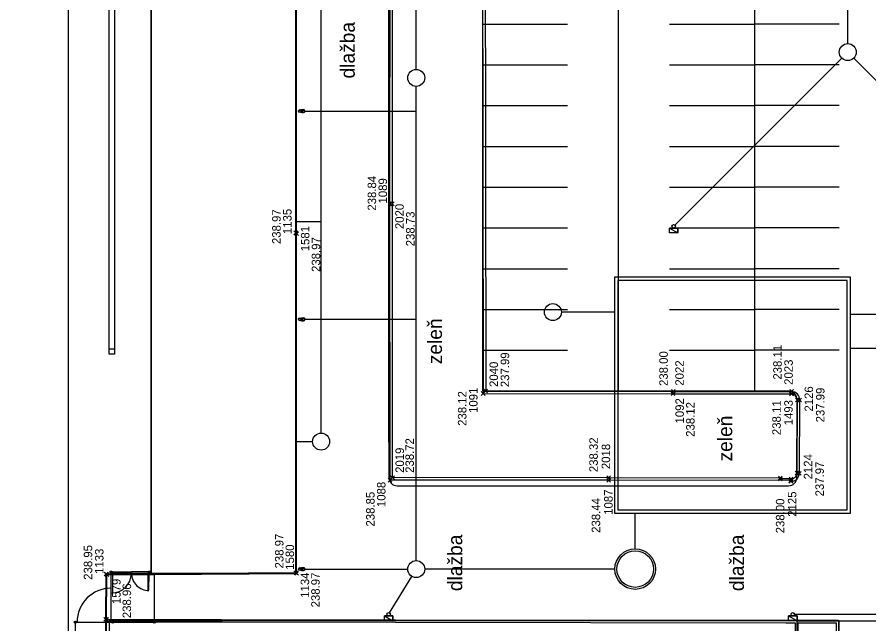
# Model space of a CAD drawing. Extents: x -264205 to -263659, y -1242401 to -1241986.
# Drawn here: x -263975.5 to -263925.3, y -1242255.2 to -1242219.4 of the extents above; entities that cross this region are included whole.
import ezdxf

# ---------------------------------------------------------------- set-up
doc = ezdxf.new("R2010")
doc.units = 0
for name, color, linetype in [('BOD_CISLO_2-3', 7, 'Continuous'), ('BOD_SYMBOL_2-3', 7, 'Continuous'), ('BOD_VYSKA_2-3', 7, 'Continuous'), ('POPIS_2-3', 7, 'Continuous'), ('PROJEKT_OBRUBNIKY_KOMUNIKACIE', 7, 'Continuous'), ('PROJEKT_TDZ_VODOROVNE', 7, 'Continuous'), ('SITUACIA_DSP_2D', 7, 'Continuous'), ('SO_20-2_OBRUBNIKY_DOLNA_HRANA', 7, 'Continuous'), ('SO_20-2_OBRUBNIKY_HORNA_HRANA', 7, 'Continuous'), ('SO_20-4_OBRUBNIKY_DOLNA_HRANA', 7, 'Continuous'), ('SO_20-4_OBRUBNIKY_HORNA_HRANA', 7, 'Continuous')]:
    doc.layers.add(name, color=color, linetype=linetype)

msp = doc.modelspace()

# ---------------------------------------------------------------- linework, layer by layer
at = {"layer": 'BOD_SYMBOL_2-3'}
for p, q in [((-263953.437, -1242230.556), (-263953.658, -1242230.335)), ((-263953.437, -1242230.335), (-263953.658, -1242230.556)), ((-263953.292, -1242230.551), (-263953.514, -1242230.329)), ((-263953.292, -1242230.329), (-263953.514, -1242230.551)), ((-263958.979, -1242232.254), (-263959.199, -1242232.032)), ((-263958.979, -1242232.032), (-263959.199, -1242232.254)), ((-263958.933, -1242232.301), (-263959.155, -1242232.079)), ((-263958.933, -1242232.079), (-263959.155, -1242232.301)), ((-263947.949, -1242241.711), (-263948.171, -1242241.49)), ((-263947.949, -1242241.49), (-263948.171, -1242241.711)), ((-263947.797, -1242241.57), (-263948.019, -1242241.35)), ((-263947.797, -1242241.35), (-263948.019, -1242241.57)), ((-263936.778, -1242241.725), (-263936.998, -1242241.505)), ((-263936.778, -1242241.505), (-263936.998, -1242241.725)), ((-263936.756, -1242241.586), (-263936.976, -1242241.366)), ((-263936.756, -1242241.366), (-263936.976, -1242241.586)), ((-263929.792, -1242241.738), (-263930.014, -1242241.518)), ((-263929.792, -1242241.518), (-263930.014, -1242241.738)), ((-263929.786, -1242241.593), (-263930.008, -1242241.372)), ((-263929.786, -1242241.372), (-263930.008, -1242241.593)), ((-263929.458, -1242242.093), (-263929.678, -1242241.872)), ((-263929.458, -1242241.872), (-263929.678, -1242242.093)), ((-263929.311, -1242242.096), (-263929.531, -1242241.876)), ((-263929.311, -1242241.876), (-263929.531, -1242242.096)), ((-263929.475, -1242246.394), (-263929.696, -1242246.173)), ((-263929.475, -1242246.173), (-263929.696, -1242246.394)), ((-263929.334, -1242246.4), (-263929.555, -1242246.18)), ((-263929.334, -1242246.18), (-263929.555, -1242246.4)), ((-263953.428, -1242246.809), (-263953.649, -1242246.588)), ((-263953.428, -1242246.588), (-263953.649, -1242246.809)), ((-263953.286, -1242246.663), (-263953.508, -1242246.441)), ((-263953.286, -1242246.441), (-263953.508, -1242246.663)), ((-263940.557, -1242246.812), (-263940.778, -1242246.592)), ((-263940.557, -1242246.592), (-263940.778, -1242246.812)), ((-263940.552, -1242246.671), (-263940.773, -1242246.45)), ((-263940.552, -1242246.45), (-263940.773, -1242246.671)), ((-263930.45, -1242246.688), (-263930.671, -1242246.467)), ((-263930.45, -1242246.467), (-263930.671, -1242246.688)), ((-263930.45, -1242246.738), (-263930.671, -1242246.516)), ((-263930.45, -1242246.516), (-263930.671, -1242246.738)), ((-263930.45, -1242246.738), (-263930.671, -1242246.516)), ((-263930.45, -1242246.516), (-263930.671, -1242246.738)), ((-263929.835, -1242246.835), (-263930.057, -1242246.613)), ((-263929.835, -1242246.613), (-263930.057, -1242246.835)), ((-263929.835, -1242246.879), (-263930.057, -1242246.657)), ((-263929.835, -1242246.657), (-263930.057, -1242246.879)), ((-263929.835, -1242246.879), (-263930.057, -1242246.657)), ((-263929.835, -1242246.657), (-263930.057, -1242246.879)), ((-263929.83, -1242246.735), (-263930.052, -1242246.514)), ((-263929.83, -1242246.514), (-263930.052, -1242246.735)), ((-263970.145, -1242252.329), (-263970.367, -1242252.107)), ((-263970.145, -1242252.107), (-263970.367, -1242252.329)), ((-263970.101, -1242252.376), (-263970.322, -1242252.154)), ((-263970.101, -1242252.154), (-263970.322, -1242252.376)), ((-263958.98, -1242252.252), (-263959.2, -1242252.031)), ((-263958.98, -1242252.031), (-263959.2, -1242252.252)), ((-263958.935, -1242252.299), (-263959.155, -1242252.078)), ((-263958.935, -1242252.078), (-263959.155, -1242252.299)), ((-263970.16, -1242254.992), (-263970.381, -1242254.772)), ((-263970.16, -1242254.772), (-263970.381, -1242254.992)), ((-263970.115, -1242254.992), (-263970.335, -1242254.772)), ((-263970.115, -1242254.772), (-263970.335, -1242254.992))]:
    msp.add_line(p, q, dxfattribs=at)
at = {"layer": 'PROJEKT_OBRUBNIKY_KOMUNIKACIE'}
for p, q in [((-263948.093, -1242087.901), (-263948.093, -1242241.458)), ((-263953.617, -1242244.458), (-263953.617, -1242093.307)), ((-263930.08, -1242241.458), (-263948.093, -1242241.458)), ((-263929.582, -1242246.53), (-263929.58, -1242241.959)), ((-263953.617, -1242244.458), (-263953.619, -1242246.529)), ((-263953.119, -1242247.03), (-263930.082, -1242247.03)), ((-263929.58, -1242254.982), (-263920.08, -1242254.982)), ((-263927.093, -1242267.983), (-263927.093, -1242254.982))]:
    msp.add_line(p, q, dxfattribs=at)
for points in [[(-264042.568, -1242294.032), (-263972.468, -1242294.032), (-263972.468, -1242187.932), (-264042.568, -1242187.932), (-264042.568, -1242294.032)], [(-263967.597, -1242197.782), (-263959.097, -1242197.782), (-263959.097, -1242252.182), (-263967.597, -1242252.182), (-263967.597, -1242197.782)], [(-263929.58, -1242254.982), (-263970.077, -1242254.982), (-263970.077, -1242263.982), (-263929.58, -1242263.982), (-263929.58, -1242254.982)]]:
    msp.add_lwpolyline(points, dxfattribs=at)
for centre, start, end in [((-263930.08, -1242241.958), 359.9785, 89.9999), ((-263953.119, -1242246.53), 179.9525, 270), ((-263930.082, -1242246.53), 270, 359.9785)]:
    msp.add_arc(centre, 0.5, start, end, dxfattribs=at)
at = {"layer": 'PROJEKT_TDZ_VODOROVNE'}
for p, q in [((-263940.088, -1242241.458), (-263940.09, -1242199.557)), ((-263932.093, -1242200.657), (-263932.093, -1242241.457)), ((-263948.093, -1242219.857), (-263943.093, -1242219.857)), ((-263937.093, -1242219.857), (-263932.093, -1242219.857)), ((-263927.093, -1242219.857), (-263932.093, -1242219.857)), ((-263948.093, -1242222.257), (-263943.093, -1242222.257)), ((-263937.093, -1242222.257), (-263932.093, -1242222.257)), ((-263927.093, -1242222.257), (-263932.093, -1242222.257)), ((-263948.093, -1242224.657), (-263943.093, -1242224.657)), ((-263937.093, -1242224.657), (-263932.093, -1242224.657)), ((-263927.093, -1242224.657), (-263932.093, -1242224.657)), ((-263948.093, -1242227.057), (-263943.093, -1242227.057)), ((-263937.093, -1242227.057), (-263932.093, -1242227.057)), ((-263927.093, -1242227.057), (-263932.093, -1242227.057)), ((-263948.093, -1242229.457), (-263943.093, -1242229.457)), ((-263937.093, -1242229.457), (-263932.093, -1242229.457)), ((-263927.093, -1242229.457), (-263932.093, -1242229.457)), ((-263948.093, -1242231.857), (-263943.093, -1242231.857)), ((-263937.093, -1242231.857), (-263932.093, -1242231.857)), ((-263927.093, -1242231.857), (-263932.093, -1242231.857)), ((-263948.093, -1242234.257), (-263943.093, -1242234.257)), ((-263937.093, -1242234.257), (-263932.093, -1242234.257)), ((-263927.093, -1242234.257), (-263932.093, -1242234.257)), ((-263948.093, -1242236.657), (-263943.093, -1242236.657)), ((-263937.093, -1242236.657), (-263932.093, -1242236.657)), ((-263927.093, -1242236.657), (-263932.093, -1242236.657)), ((-263948.093, -1242239.057), (-263943.093, -1242239.057)), ((-263937.093, -1242239.057), (-263932.093, -1242239.057)), ((-263927.093, -1242239.057), (-263932.093, -1242239.057))]:
    msp.add_line(p, q, dxfattribs=at)
at = {"layer": 'SITUACIA_DSP_2D'}
for p, q in [((-263948.093, -1242087.901), (-263948.093, -1242241.458)), ((-263953.617, -1242244.458), (-263953.617, -1242093.307)), ((-263952, -1242222.527), (-263952, -1242182)), ((-263972.468, -1242294.032), (-263972.468, -1242187.932)), ((-263957.597, -1242243.932), (-263957.597, -1242193.383)), ((-263967.597, -1242252.182), (-263967.597, -1242197.782)), ((-263967.593, -1242252.182), (-263967.593, -1242197.782)), ((-263967.593, -1242252.182), (-263967.593, -1242197.782)), ((-263959.097, -1242197.782), (-263959.093, -1242252.182)), ((-263959.097, -1242197.782), (-263959.097, -1242252.182)), ((-263959.093, -1242197.782), (-263959.093, -1242252.182)), ((-263926.593, -1242221.011), (-263926.593, -1242205.252)), ((-263970.07, -1242239.282), (-263970.071, -1242210.684)), ((-263969.77, -1242210.682), (-263969.77, -1242239.282)), ((-263936.772, -1242231.691), (-263926.947, -1242221.865)), ((-263916.414, -1242231.691), (-263926.24, -1242221.865)), ((-263952, -1242251.432), (-263952, -1242223.527)), ((-263958.799, -1242224.912), (-263958.762, -1242224.912)), ((-263958.799, -1242225.052), (-263958.762, -1242225.052)), ((-263958.762, -1242224.912), (-263958.742, -1242224.892)), ((-263958.762, -1242225.052), (-263958.742, -1242225.072)), ((-263958.742, -1242224.892), (-263958.637, -1242224.892)), ((-263958.742, -1242225.072), (-263958.637, -1242225.072)), ((-263958.575, -1242224.982), (-263952, -1242224.982)), ((-263959.097, -1242231.482), (-263957.597, -1242231.482)), ((-263937.093, -1242231.862), (-263936.593, -1242231.862)), ((-263937.093, -1242232.152), (-263937.093, -1242231.862)), ((-263937.093, -1242231.862), (-263936.593, -1242232.152)), ((-263937.093, -1242231.862), (-263936.593, -1242232.152)), ((-263936.593, -1242231.862), (-263937.093, -1242231.862)), ((-263936.593, -1242232.152), (-263937.093, -1242232.152)), ((-263936.593, -1242231.862), (-263936.593, -1242232.152)), ((-263936.593, -1242232.152), (-263936.593, -1242231.862)), ((-263926.43, -1242234.749), (-263940.33, -1242234.749)), ((-263940.33, -1242234.749), (-263940.33, -1242248.649)), ((-263926.63, -1242234.949), (-263940.13, -1242234.949)), ((-263940.13, -1242234.949), (-263940.13, -1242248.449)), ((-263926.63, -1242248.449), (-263926.63, -1242234.949)), ((-263926.43, -1242248.649), (-263926.43, -1242234.749)), ((-263958.799, -1242237.162), (-263958.762, -1242237.162)), ((-263958.762, -1242237.162), (-263958.742, -1242237.142)), ((-263958.742, -1242237.142), (-263958.637, -1242237.142)), ((-263940.33, -1242236.811), (-263943.454, -1242236.811)), ((-263919.13, -1242236.949), (-263926.43, -1242236.949)), ((-263958.799, -1242237.302), (-263958.762, -1242237.302)), ((-263958.762, -1242237.302), (-263958.742, -1242237.322)), ((-263958.742, -1242237.322), (-263958.637, -1242237.322)), ((-263958.575, -1242237.232), (-263952, -1242237.232)), ((-263969.77, -1242238.982), (-263970.07, -1242238.982)), ((-263907.219, -1242238.949), (-263926.43, -1242238.949)), ((-263969.77, -1242239.282), (-263970.07, -1242239.282)), ((-263930.081, -1242241.458), (-263948.093, -1242241.458)), ((-263929.582, -1242246.53), (-263929.581, -1242241.959)), ((-263959.097, -1242244.432), (-263958.097, -1242244.432)), ((-263953.617, -1242244.458), (-263953.619, -1242246.529)), ((-263953.119, -1242247.03), (-263930.082, -1242247.03)), ((-263940.33, -1242248.649), (-263926.43, -1242248.649)), ((-263940.13, -1242248.449), (-263926.63, -1242248.449)), ((-263939.13, -1242248.649), (-263939.13, -1242250.737)), ((-263970.018, -1242252.152), (-263970.018, -1242252.052)), ((-263970.018, -1242252.052), (-263969.918, -1242252.052)), ((-263969.918, -1242252.152), (-263970.018, -1242252.152)), ((-263970.005, -1242252.14), (-263970.005, -1242252.065)), ((-263970.005, -1242252.065), (-263969.93, -1242252.065)), ((-263969.93, -1242252.14), (-263970.005, -1242252.14)), ((-263969.93, -1242252.14), (-263969.98, -1242252.14)), ((-263969.98, -1242252.14), (-263969.98, -1242252.24)), ((-263969.968, -1242252.152), (-263969.968, -1242252.202)), ((-263969.968, -1242252.202), (-263969.868, -1242252.202)), ((-263969.955, -1242253.327), (-263969.955, -1242252.19)), ((-263969.955, -1242252.19), (-263969.88, -1242252.19)), ((-263969.93, -1242252.065), (-263969.93, -1242252.14)), ((-263969.918, -1242252.052), (-263969.918, -1242252.152)), ((-263969.918, -1242252.102), (-263968.78, -1242252.102)), ((-263969.918, -1242252.177), (-263969.918, -1242252.102)), ((-263968.78, -1242252.177), (-263969.918, -1242252.177)), ((-263969.88, -1242252.19), (-263969.88, -1242253.327)), ((-263969.868, -1242252.202), (-263969.868, -1242252.177)), ((-263968.78, -1242252.102), (-263968.78, -1242252.177)), ((-263967.768, -1242252.102), (-263968.755, -1242252.102)), ((-263968.755, -1242252.102), (-263968.755, -1242252.177)), ((-263968.755, -1242252.177), (-263967.768, -1242252.177)), ((-263967.818, -1242252.202), (-263967.818, -1242252.177)), ((-263967.718, -1242252.202), (-263967.818, -1242252.202)), ((-263967.805, -1242252.19), (-263967.807, -1242253.177)), ((-263967.73, -1242252.19), (-263967.805, -1242252.19)), ((-263967.768, -1242252.152), (-263967.768, -1242252.052)), ((-263967.768, -1242252.052), (-263967.668, -1242252.052)), ((-263967.768, -1242252.177), (-263967.768, -1242252.102)), ((-263967.668, -1242252.152), (-263967.768, -1242252.152)), ((-263967.755, -1242252.14), (-263967.755, -1242252.065)), ((-263967.755, -1242252.065), (-263967.68, -1242252.065)), ((-263967.755, -1242252.14), (-263967.705, -1242252.14)), ((-263967.68, -1242252.14), (-263967.755, -1242252.14)), ((-263967.732, -1242253.177), (-263967.73, -1242252.19)), ((-263967.718, -1242252.152), (-263967.718, -1242252.202)), ((-263967.705, -1242252.14), (-263967.705, -1242252.24)), ((-263967.68, -1242252.065), (-263967.68, -1242252.14)), ((-263967.668, -1242252.052), (-263967.668, -1242252.152)), ((-263959.097, -1242252.182), (-263967.597, -1242252.182)), ((-263959.093, -1242252.182), (-263967.593, -1242252.182)), ((-263959.093, -1242252.182), (-263967.593, -1242252.182)), ((-263967.418, -1242252.182), (-263967.418, -1242255.057)), ((-263958.799, -1242251.862), (-263958.762, -1242251.862)), ((-263958.799, -1242252.002), (-263958.762, -1242252.002)), ((-263958.762, -1242251.862), (-263958.742, -1242251.842)), ((-263958.762, -1242252.002), (-263958.742, -1242252.022)), ((-263958.742, -1242251.842), (-263958.637, -1242251.842)), ((-263958.742, -1242252.022), (-263958.637, -1242252.022)), ((-263958.575, -1242251.932), (-263952.5, -1242251.932)), ((-263940.302, -1242251.932), (-263951.5, -1242251.932)), ((-263969.98, -1242252.24), (-263969.955, -1242252.24)), ((-263967.705, -1242252.24), (-263967.73, -1242252.24)), ((-263953.57, -1242254.506), (-263952.26, -1242252.359)), ((-263969.968, -1242255.057), (-263969.968, -1242253.057)), ((-263953.87, -1242254.692), (-263953.37, -1242254.692)), ((-263953.87, -1242254.982), (-263953.87, -1242254.692)), ((-263953.87, -1242254.692), (-263953.37, -1242254.982)), ((-263953.87, -1242254.692), (-263953.37, -1242254.982)), ((-263953.37, -1242254.692), (-263953.87, -1242254.692)), ((-263953.37, -1242254.692), (-263953.37, -1242254.982)), ((-263953.37, -1242254.982), (-263953.37, -1242254.692)), ((-263930.08, -1242254.692), (-263929.58, -1242254.692)), ((-263930.08, -1242254.982), (-263930.08, -1242254.692)), ((-263930.08, -1242254.692), (-263929.58, -1242254.982)), ((-263930.08, -1242254.692), (-263929.58, -1242254.982)), ((-263929.58, -1242254.692), (-263930.08, -1242254.692)), ((-263929.73, -1242254.592), (-263920.595, -1242254.592)), ((-263929.58, -1242254.692), (-263929.58, -1242254.982)), ((-263929.58, -1242254.982), (-263929.58, -1242254.692)), ((-263972.128, -1242255.057), (-263972.008, -1242255.057)), ((-263972.068, -1242255.117), (-263972.068, -1242254.997)), ((-263972.068, -1242255.057), (-263967.418, -1242255.057)), ((-263972.068, -1242294.432), (-263972.068, -1242255.057)), ((-263929.58, -1242254.982), (-263970.077, -1242254.982)), ((-263970.077, -1242254.982), (-263970.077, -1242263.982)), ((-263969.928, -1242255.057), (-263969.808, -1242255.057)), ((-263969.868, -1242255.117), (-263969.868, -1242254.997)), ((-263967.478, -1242255.057), (-263967.358, -1242255.057)), ((-263967.418, -1242255.117), (-263967.418, -1242254.997)), ((-263953.37, -1242254.982), (-263953.87, -1242254.982)), ((-263929.58, -1242254.982), (-263930.08, -1242254.982)), ((-263929.58, -1242263.982), (-263929.58, -1242254.982))]:
    msp.add_line(p, q, dxfattribs=at)
for centre, radius in [((-263926.593, -1242221.511), 0.5), ((-263952, -1242223.027), 0.5), ((-263958.847, -1242224.982), 0.085), ((-263958.847, -1242224.982), 0.0625), ((-263958.637, -1242224.982), 0.0625), ((-263936.843, -1242231.762), 0.1), ((-263943.954, -1242236.811), 0.5), ((-263958.847, -1242237.232), 0.085), ((-263958.847, -1242237.232), 0.0625), ((-263958.637, -1242237.232), 0.0625), ((-263957.597, -1242244.432), 0.5), ((-263939.107, -1242251.932), 1.195), ((-263939.107, -1242251.932), 1.075), ((-263952, -1242251.932), 0.5), ((-263958.847, -1242251.932), 0.085), ((-263958.847, -1242251.932), 0.0625), ((-263958.637, -1242251.932), 0.0625), ((-263953.62, -1242254.592), 0.1), ((-263929.83, -1242254.592), 0.1), ((-263972.068, -1242255.057), 0.06), ((-263969.868, -1242255.057), 0.06), ((-263967.418, -1242255.057), 0.06)]:
    msp.add_circle(centre, radius, dxfattribs=at)
for centre, radius, start, end in [((-263958.637, -1242224.982), 0.09, 270, 90), ((-263958.637, -1242237.232), 0.09, 270, 90), ((-263930.081, -1242241.958), 0.5, 359.9785, 89.9999), ((-263953.119, -1242246.53), 0.5, 179.9525, 270), ((-263930.082, -1242246.53), 0.5, 270, 359.9785), ((-263969.943, -1242252.165), 1.175, 269.3905, 359.3905), ((-263967.743, -1242252.165), 1.025, 180.6095, 270.6095), ((-263958.637, -1242251.932), 0.09, 270, 90), ((-263969.968, -1242255.057), 2, 90, 180)]:
    msp.add_arc(centre, radius, start, end, dxfattribs=at)
for centre in [(-263969.943, -1242252.165), (-263969.943, -1242252.165), (-263967.743, -1242252.165)]:
    msp.add_ellipse(centre, major_axis=(0, 0.0125), ratio=0.999995, dxfattribs=at)
at = {"layer": 'SO_20-2_OBRUBNIKY_DOLNA_HRANA'}
for p, q in [((-263930.231, -1242255.088), (-263929.686, -1242255.089)), ((-263929.686, -1242255.089), (-263929.727, -1242263.714))]:
    msp.add_line(p, q, dxfattribs=at)
for points in [[(-263970.225, -1242255.029), (-263963.43, -1242255.035), (-263953.224, -1242255.054), (-263930.231, -1242255.088)], [(-263927.183, -1242254.936), (-263927.134, -1242254.939), (-263927.032, -1242263.694)]]:
    msp.add_lwpolyline(points, dxfattribs=at)
at = {"layer": 'SO_20-2_OBRUBNIKY_HORNA_HRANA'}
for p, q in [((-263970.27, -1242254.881), (-263970.225, -1242254.882)), ((-263930.229, -1242254.938), (-263929.52, -1242254.945)), ((-263929.536, -1242255.089), (-263929.577, -1242263.713)), ((-263929.536, -1242255.089), (-263927.277, -1242255.089))]:
    msp.add_line(p, q, dxfattribs=at)
for points in [[(-263970.27, -1242270.832), (-263970.272, -1242265.906), (-263970.272, -1242263.853), (-263970.27, -1242254.881)], [(-263970.227, -1242270.832), (-263970.227, -1242265.907), (-263970.227, -1242263.854), (-263970.225, -1242254.882)], [(-263970.225, -1242254.882), (-263963.483, -1242254.892), (-263953.227, -1242254.91), (-263930.229, -1242254.938)], [(-263929.52, -1242254.945), (-263927.183, -1242254.936)], [(-263927.277, -1242255.089), (-263927.18, -1242263.695)]]:
    msp.add_lwpolyline(points, dxfattribs=at)
at = {"layer": 'SO_20-4_OBRUBNIKY_DOLNA_HRANA'}
for p, q in [((-263947.908, -1242241.46), (-263936.866, -1242241.476)), ((-263936.866, -1242241.476), (-263929.897, -1242241.482)), ((-263929.444, -1242246.29), (-263929.421, -1242241.986)), ((-263930.561, -1242246.577), (-263930.561, -1242246.627))]:
    msp.add_line(p, q, dxfattribs=at)
for points in [[(-263948.011, -1242159.299), (-263947.969, -1242181.806), (-263947.945, -1242208.885), (-263947.934, -1242214.486), (-263947.908, -1242241.46)], [(-263930.561, -1242246.577), (-263940.662, -1242246.56), (-263953.397, -1242246.552), (-263953.403, -1242230.44), (-263953.398, -1242215.556)]]:
    msp.add_lwpolyline(points, dxfattribs=at)
for centre, major_axis, ratio, start_param, end_param in [((-263929.917, -1242241.977), (-0.446, 0.216), 0.999926, 3.57519, 5.124108), ((-263929.934, -1242246.277), (0.166, 0.463), 0.996255, 3.462651, 5.02822)]:
    msp.add_ellipse(centre, major_axis=major_axis, ratio=ratio, start_param=start_param, end_param=end_param, dxfattribs=at)
at = {"layer": 'SO_20-4_OBRUBNIKY_HORNA_HRANA'}
for p, q in [((-263948.06, -1242241.6), (-263936.888, -1242241.615)), ((-263936.888, -1242241.615), (-263929.903, -1242241.628)), ((-263929.568, -1242241.982), (-263929.585, -1242246.283)), ((-263929.941, -1242246.624), (-263930.561, -1242246.627)), ((-263929.946, -1242246.724), (-263929.946, -1242246.768))]:
    msp.add_line(p, q, dxfattribs=at)
for points in [[(-263948.158, -1242159.282), (-263948.117, -1242181.8), (-263948.089, -1242208.869), (-263948.089, -1242214.486), (-263948.06, -1242241.6)], [(-263970.256, -1242252.218), (-263959.09, -1242252.141), (-263959.089, -1242232.143), (-263959.091, -1242212.166)], [(-263970.225, -1242254.882), (-263970.211, -1242252.265), (-263959.045, -1242252.188), (-263959.044, -1242232.19), (-263959.046, -1242212.167)], [(-263929.946, -1242246.724), (-263940.667, -1242246.702), (-263953.539, -1242246.698), (-263953.547, -1242230.445), (-263953.543, -1242215.554)], [(-263970.27, -1242254.882), (-263970.256, -1242252.218)]]:
    msp.add_lwpolyline(points, dxfattribs=at)
for centre, major_axis, ratio, start_param, end_param in [((-263929.917, -1242241.977), (-0.24, 0.254), 0.999949, 3.939741, 5.485037), ((-263929.933, -1242246.276), (-0.037, 0.346), 0.999672, 3.010538, 4.584796)]:
    msp.add_ellipse(centre, major_axis=major_axis, ratio=ratio, start_param=start_param, end_param=end_param, dxfattribs=at)

# ---------------------------------------------------------------- texts
at = {"layer": 'BOD_CISLO_2-3'}
for s, p in [('1089', (-263953.718, -1242230.419)), ('2020', (-263952.734, -1242231.924)), ('1135', (-263959.34, -1242232.216)), ('1581', (-263958.288, -1242233.231)), ('2023', (-263929.829, -1242241.092)), ('2040', (-263947.184, -1242241.215)), ('2022', (-263936.248, -1242241.138)), ('1091', (-263948.388, -1242242.745)), ('2126', (-263928.636, -1242242.663)), ('1092', (-263936.242, -1242243.364)), ('1493', (-263929.834, -1242243.471)), ('2018', (-263940.584, -1242246.05)), ('2019', (-263952.721, -1242246.271)), ('2124', (-263928.681, -1242246.654)), ('1088', (-263953.809, -1242248.281)), ('1087', (-263940.435, -1242248.738)), ('2125', (-263929.618, -1242248.853)), ('1580', (-263959.191, -1242251.969)), ('1133', (-263970.412, -1242252.218)), ('1134', (-263958.305, -1242253.622)), ('1579', (-263969.403, -1242253.988))]:
    msp.add_text(s, height=0.5, rotation=90, dxfattribs=at).set_placement(p)
at = {"layer": 'BOD_VYSKA_2-3'}
for s, p in [('238.84', (-263954.36, -1242230.839)), ('238.97', (-263959.98, -1242232.807)), ('238.73', (-263952.098, -1242232.938)), ('238.97', (-263957.653, -1242234.447)), ('238.00', (-263937.189, -1242241.157)), ('238.11', (-263930.481, -1242240.784)), ('237.99', (-263946.528, -1242241.227)), ('238.12', (-263949.044, -1242243.504)), ('237.99', (-263927.963, -1242243.299)), ('238.12', (-263935.612, -1242244.148)), ('238.11', (-263930.537, -1242244.048)), ('238.72', (-263952.137, -1242246.27)), ('238.32', (-263941.31, -1242246.229)), ('237.97', (-263928.001, -1242247.653)), ('238.85', (-263954.451, -1242249.428)), ('238.44', (-263941.169, -1242249.8)), ('238.00', (-263930.324, -1242249.828)), ('238.97', (-263959.814, -1242251.894)), ('238.95', (-263971.074, -1242252.562)), ('238.97', (-263957.68, -1242254.185)), ('238.96', (-263968.788, -1242254.821))]:
    msp.add_text(s, height=0.5, rotation=90, dxfattribs=at).set_placement(p)
at = {"layer": 'POPIS_2-3'}
for s, p in [('dlažba', (-263955.618, -1242223.063)), ('zeleň', (-263950.485, -1242239.877)), ('zeleň', (-263933.396, -1242245.598)), ('dlažba', (-263949.291, -1242253.229)), ('dlažba', (-263932.706, -1242253.229))]:
    msp.add_text(s, height=0.8438, rotation=90, dxfattribs=at).set_placement(p)

doc.saveas('drawing.dxf')
